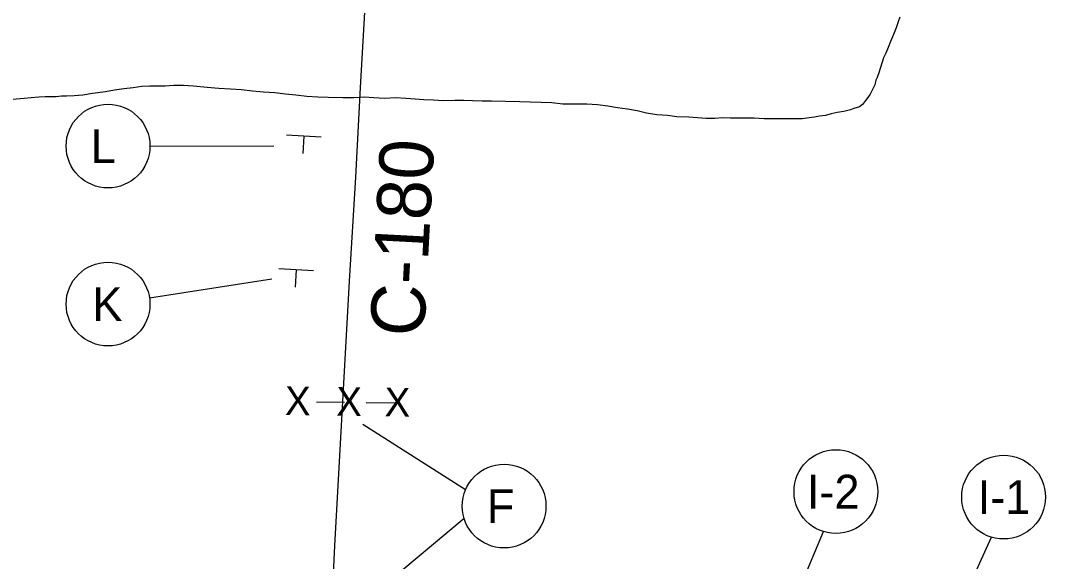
# Model space of a CAD drawing. Extents: x 1 to 1971, y -2 to 1107.
# Drawn here: x 1655.229 to 1659.967, y 1089.477 to 1091.977 of the extents above; entities that cross this region are included whole.
import ezdxf

# ---------------------------------------------------------------- set-up
doc = ezdxf.new("R2010")
doc.units = 0
for name, color, linetype in [('GM_X_County_Road', 7, 'Continuous'), ('GM_X_County_Road_Text', 7, 'Continuous'), ('GM_X_Minor_River', 7, 'Continuous'), ('SH_Text', 7, 'Continuous'), ('SN_P_Signs', 7, 'Continuous')]:
    doc.layers.add(name, color=color, linetype=linetype)

msp = doc.modelspace()

# ---------------------------------------------------------------- linework, layer by layer
at = {"layer": 'GM_X_County_Road'}
msp.add_lwpolyline([(1656.6538, 1088.9713), (1656.6824, 1089.549), (1656.7502, 1090.7723), (1656.779, 1091.2527), (1656.8004, 1091.6678), (1656.8346, 1092.2577), (1656.8383, 1092.3049), (1656.8451, 1092.3768), (1656.8483, 1092.4109)], dxfattribs=at)
msp.add_lwpolyline([(1656.6538, 1088.9713), (1656.6824, 1089.549), (1656.7502, 1090.7723), (1656.779, 1091.2527), (1656.8004, 1091.6678), (1656.8346, 1092.2577), (1656.8383, 1092.3049), (1656.8451, 1092.3768), (1656.8483, 1092.4109)], dxfattribs=at)
at = {"layer": 'GM_X_Minor_River'}
for points in [[(1659.2936, 1091.9921), (1659.2855, 1091.9707), (1659.2774, 1091.9439), (1659.264, 1091.9119), (1659.2505, 1091.8798), (1659.2398, 1091.8531), (1659.229, 1091.8264), (1659.2183, 1091.805), (1659.1967, 1091.7355), (1659.1886, 1091.7141), (1659.1832, 1091.7008), (1659.1778, 1091.6794), (1659.1671, 1091.658), (1659.1563, 1091.6367), (1659.1456, 1091.6206), (1659.1349, 1091.6073), (1659.1214, 1091.5886), (1659.108, 1091.5779), (1659.0813, 1091.57), (1659.0652, 1091.5647), (1659.0357, 1091.5568), (1659.0036, 1091.5515), (1658.9769, 1091.5463), (1658.9501, 1091.5383), (1658.9233, 1091.5357), (1658.8992, 1091.5305), (1658.8751, 1091.5279), (1658.843, 1091.5226), (1658.8082, 1091.5227), (1658.752, 1091.5229), (1658.7092, 1091.5231), (1658.6664, 1091.5232), (1658.6209, 1091.526), (1658.5835, 1091.5261), (1658.546, 1091.5262), (1658.5112, 1091.5263), (1658.4738, 1091.5265), (1658.439, 1091.5239), (1658.3988, 1091.524), (1658.3587, 1091.5268), (1658.3186, 1091.5296)], [(1658.3186, 1091.5296), (1658.2624, 1091.5325), (1658.2196, 1091.538), (1658.1714, 1091.5408), (1658.1233, 1091.549), (1658.0805, 1091.5598), (1658.035, 1091.568), (1657.9896, 1091.5735), (1657.9441, 1091.5817), (1657.8959, 1091.5872), (1657.8478, 1091.59), (1657.7996, 1091.5901), (1657.7354, 1091.5904), (1657.6846, 1091.5959), (1657.6364, 1091.5987), (1657.5856, 1091.5989), (1657.5374, 1091.6017), (1657.4063, 1091.6048), (1657.3635, 1091.6049), (1657.318, 1091.6051), (1657.2779, 1091.6079), (1657.2377, 1091.608), (1657.1815, 1091.6055), (1657.1387, 1091.6083), (1657.0933, 1091.6111), (1657.0531, 1091.6139), (1657.0103, 1091.6167), (1656.9622, 1091.6196), (1656.9113, 1091.6171), (1656.8632, 1091.6199), (1656.8177, 1091.6227), (1656.7695, 1091.6202), (1656.7187, 1091.6203), (1656.6518, 1091.6206), (1656.6036, 1091.6234), (1656.5528, 1091.6262), (1656.502, 1091.6317), (1656.4538, 1091.6372), (1656.4057, 1091.6428), (1656.3521, 1091.6456), (1656.3013, 1091.6511), (1656.2505, 1091.6566), (1656.1997, 1091.6595), (1656.1462, 1091.6623), (1656.0927, 1091.6678), (1656.0285, 1091.6734), (1655.983, 1091.6762), (1655.9375, 1091.6764), (1655.8973, 1091.6738), (1655.8626, 1091.6739), (1655.8278, 1091.674), (1655.7903, 1091.6715), (1655.7501, 1091.6663), (1655.7073, 1091.661), (1655.6645, 1091.6558), (1655.6217, 1091.6479), (1655.5628, 1091.6401), (1655.5173, 1091.6322), (1655.4771, 1091.6297), (1655.4424, 1091.6271), (1655.4183, 1091.6272), (1655.3942, 1091.6246), (1655.3701, 1091.6247), (1655.3433, 1091.6247), (1655.3139, 1091.6222), (1655.2791, 1091.6196), (1655.247, 1091.617), (1655.156, 1091.6093)]]:
    msp.add_lwpolyline(points, dxfattribs=at)
at = {"layer": 'SH_Text'}
for p, q in [((1656.4004, 1091.3968), (1655.8275, 1091.3951)), ((1656.3918, 1090.7809), (1655.8256, 1090.6937)), ((1656.811, 1090.1106), (1657.2866, 1089.8088)), ((1656.7115, 1089.2016), (1657.2794, 1089.6766)), ((1658.7325, 1089.1178), (1658.9411, 1089.6146)), ((1659.4825, 1089.0736), (1659.7177, 1089.5889))]:
    msp.add_line(p, q, dxfattribs=at)
for centre in [(1655.6339, 1091.3968), (1655.6339, 1090.6665), (1658.9984, 1089.7995), (1659.7736, 1089.7743), (1657.4647, 1089.7328)]:
    msp.add_circle(centre, 0.1936, dxfattribs=at)
at = {"layer": 'SN_P_Signs'}
for p, q in [((1656.6184, 1091.4383), (1656.4586, 1091.4466)), ((1656.5385, 1091.4425), (1656.5344, 1091.3626)), ((1656.5835, 1090.8203), (1656.4237, 1090.8286)), ((1656.5036, 1090.8244), (1656.4995, 1090.7445)), ((1656.5973, 1090.2149), (1656.7275, 1090.2132)), ((1656.8276, 1090.2119), (1656.9645, 1090.2101))]:
    msp.add_line(p, q, dxfattribs=at)

# ---------------------------------------------------------------- texts
at = {"layer": 'GM_X_County_Road_Text'}
msp.add_text('C-180', height=0.25, rotation=86.9706, dxfattribs=at).set_placement((1657.0943, 1090.5122))
at = {"layer": 'SH_Text'}
for s, p in [('L', (1655.5536, 1091.3188)), ('K', (1655.5614, 1090.5885)), ('I-2', (1658.8642, 1089.7215)), ('I-1', (1659.6537, 1089.6963)), ('F', (1657.385, 1089.6548))]:
    msp.add_text(s, height=0.156, dxfattribs=at).set_placement(p)
at = {"layer": 'SN_P_Signs'}
for p in [(1656.4509, 1090.1533), (1656.6878, 1090.1502), (1656.9114, 1090.1472)]:
    msp.add_text('X', height=0.1333, rotation=359.2514, dxfattribs=at).set_placement(p)

doc.saveas('drawing.dxf')
